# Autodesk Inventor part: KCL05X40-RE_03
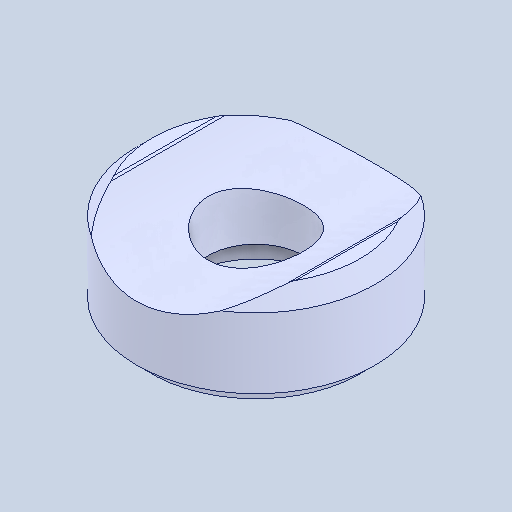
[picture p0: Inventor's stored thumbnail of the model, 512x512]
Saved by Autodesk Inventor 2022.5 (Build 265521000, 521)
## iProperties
Created: 2024-08
Part Number: KCL05X40-RE_03
Material: 一般
Document SubType Name: Modeling
Designer: ImaoCorp
Density: 1 g/cm^3
Appearance: 既定
Author: ImaoCorp
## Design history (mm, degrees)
feature "KCL05X40-RE_03"
node "ソリッド1"
